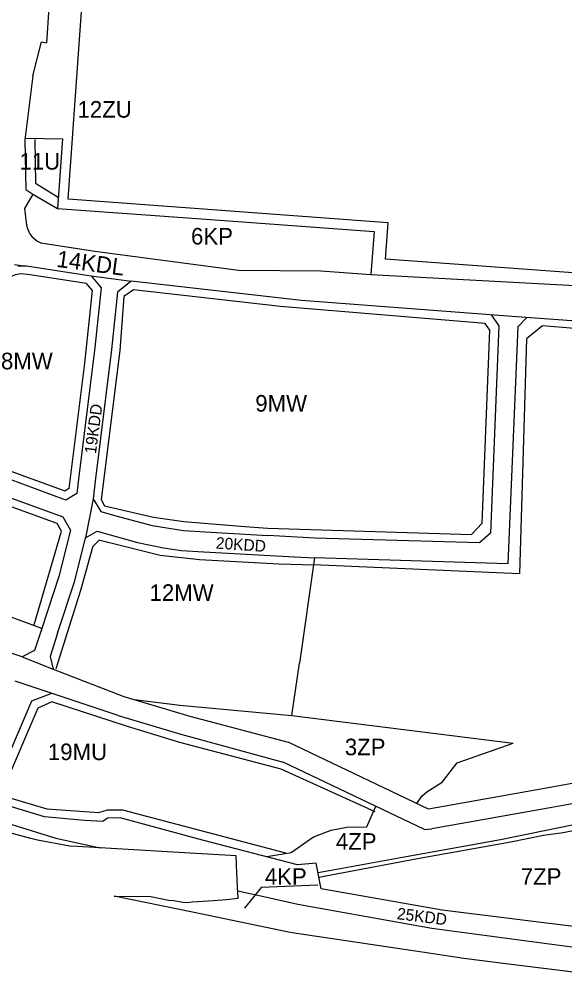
# Model space of a CAD drawing. Extents: x 7428203 to 7432868, y 5542672 to 5545406.
# Drawn here: x 7432004 to 7432333, y 5542818 to 5543396 of the extents above; entities that cross this region are included whole.
import ezdxf

# ---------------------------------------------------------------- set-up
doc = ezdxf.new("R2010")
doc.units = 0
for name, color, linetype in [('granica_planu', 7, 'Continuous'), ('linie_rozgraniczajace', 7, 'Continuous'), ('linie_zabudowy_nieprzekraczalne', 7, 'Continuous'), ('oznaczenia_przeznaczen', 7, 'Continuous')]:
    doc.layers.add(name, color=color, linetype=linetype)

msp = doc.modelspace()

# ---------------------------------------------------------------- linework, layer by layer
at = {"layer": 'granica_planu'}
msp.add_lwpolyline([(7432366.07, 5542818.36), (7432299.15, 5542826.68), (7432270.59, 5542830.22), (7432269.61, 5542830.37), (7432247.14, 5542833.74), (7432240.24, 5542834.78), (7432168.81, 5542845.49), (7432167.6, 5542845.74), (7432108.76, 5542857.84), (7432061.43, 5542867.58), (7432083.54, 5542867.28), (7432094.2, 5542865.19), (7432097.52, 5542864.92), (7432099.5, 5542864.5), (7432103.13, 5542863.99), (7432105.41, 5542863.84), (7432108.51, 5542864.06), (7432121.35, 5542864.94), (7432129.15, 5542865.52), (7432136.19, 5542866.32), (7432136, 5542870.15), (7432135.89, 5542872.37), (7432135.64, 5542878.11), (7432135.51, 5542881.51), (7432134.96, 5542891.84), (7432107.31, 5542893.48), (7432059.63, 5542896.3), (7432052.98, 5542896.69), (7432039.2, 5542897.51), (7432034.8, 5542897.77), (7432015.34, 5542901.29), (7432011.22, 5542902.36), (7431994.8, 5542906.65)], dxfattribs=at)
at = {"layer": 'linie_rozgraniczajace'}
for p, q in [((7432037.23, 5543621.26), (7432020.68, 5543381.69)), ((7432033.73, 5543287.48), (7432057.57, 5543619.82)), ((7432012.53, 5543361.9), (7432007.71, 5543323.27)), ((7432007.71, 5543323.27), (7432008.21, 5543293.28)), ((7432008.21, 5543293.28), (7432012.56, 5543290.59)), ((7432226.56, 5543273.31), (7432033.73, 5543287.48)), ((7432224.95, 5543251.39), (7432226.56, 5543273.31)), ((7432008.74, 5543271.82), (7432009.24, 5543269.81)), ((7432009.24, 5543269.81), (7432010.01, 5543267.87)), ((7432010.01, 5543267.87), (7432010.69, 5543266.65)), ((7432010.69, 5543266.65), (7432011.86, 5543265.07)), ((7432011.86, 5543265.07), (7432014.95, 5543262.4)), ((7432014.95, 5543262.4), (7432017.22, 5543261.23)), ((7432017.22, 5543261.23), (7432049.82, 5543256.21)), ((7432505.88, 5543230.9), (7432224.95, 5543251.39)), ((7432047.55, 5543241.39), (7432071.7, 5543238.19)), ((7432071.7, 5543238.19), (7432063.48, 5543231.48)), ((7432063.48, 5543231.48), (7432059.85, 5543196.95)), ((7432293.36, 5543211.37), (7432289.12, 5543217.69)), ((7432059.85, 5543196.95), (7432050.01, 5543117.61)), ((7432050.01, 5543117.61), (7432048.79, 5543107.04)), ((7432048.79, 5543107.04), (7432044.22, 5543083.37)), ((7432048.79, 5543107.04), (7432053.55, 5543099.39)), ((7432053.55, 5543099.39), (7432062.57, 5543096.75)), ((7432062.57, 5543096.75), (7432084.4, 5543090.89)), ((7432044.22, 5543083.37), (7432051.3, 5543087.55)), ((7432051.3, 5543087.55), (7432075.64, 5543080.66)), ((7432084.4, 5543090.89), (7432103.35, 5543087.86)), ((7432103.35, 5543087.86), (7432116.25, 5543087)), ((7432037.72, 5543057.46), (7432044.22, 5543083.37)), ((7432116.25, 5543087), (7432154.1, 5543084.92)), ((7432182.5, 5543083.35), (7432154.1, 5543084.92)), ((7432075.64, 5543080.66), (7432091.23, 5543077.48)), ((7432091.23, 5543077.48), (7432102.09, 5543075.91)), ((7432102.09, 5543075.91), (7432115.52, 5543075.02)), ((7432115.52, 5543075.02), (7432170.23, 5543072.01)), ((7432170.23, 5543072.01), (7432182.15, 5543071.36)), ((7432182.15, 5543071.36), (7432173.17, 5543007.95)), ((7432017.85, 5543028.79), (7431919, 5543064.95)), ((7432027.43, 5543025.93), (7432037.72, 5543057.46)), ((7432005.96, 5543011.7), (7432024.64, 5543004.41)), ((7432168.62, 5542976.37), (7432173.17, 5543007.95)), ((7432001.68, 5542997.32), (7432063.09, 5542976.74)), ((7432011.78, 5542985.25), (7432023.96, 5542989.85)), ((7431989.67, 5542933.23), (7432011.78, 5542985.25)), ((7432063.97, 5542976.44), (7432103.64, 5542964.58)), ((7432168.62, 5542976.37), (7432302.06, 5542959.76)), ((7432103.64, 5542964.58), (7432103.98, 5542964.48)), ((7432103.98, 5542964.48), (7432163.4, 5542948.38)), ((7432250.93, 5542919.95), (7432166.31, 5542960.28)), ((7432248.57, 5542907.78), (7432163.4, 5542948.38)), ((7432466.38, 5542946.5), (7432326.44, 5542921.16)), ((7432019.53, 5542915.43), (7431995.04, 5542922.73)), ((7432326.39, 5542921.15), (7432253.03, 5542908.13)), ((7432043.53, 5542913.22), (7432019.53, 5542915.43)), ((7432057.53, 5542914.56), (7432054.7, 5542912.58)), ((7432065.12, 5542914.7), (7432057.53, 5542914.56)), ((7432114.78, 5542901.27), (7432065.12, 5542914.7)), ((7432054.7, 5542912.58), (7432043.53, 5542913.22)), ((7432011.22, 5542902.36), (7431994.8, 5542906.65)), ((7432015.34, 5542901.29), (7432011.22, 5542902.36)), ((7432034.8, 5542897.77), (7432015.34, 5542901.29)), ((7432039.2, 5542897.51), (7432034.8, 5542897.77)), ((7432052.98, 5542896.69), (7432039.2, 5542897.51)), ((7432059.63, 5542896.3), (7432052.98, 5542896.69)), ((7432171.89, 5542886.38), (7432114.78, 5542901.27)), ((7432107.31, 5542893.48), (7432059.63, 5542896.3)), ((7432134.96, 5542891.84), (7432107.31, 5542893.48)), ((7432135.51, 5542881.51), (7432134.96, 5542891.84)), ((7432183.24, 5542887.35), (7432171.89, 5542886.38)), ((7432186.29, 5542871.95), (7432183.24, 5542887.35)), ((7432135.64, 5542878.11), (7432135.51, 5542881.51)), ((7432135.89, 5542872.37), (7432135.64, 5542878.11)), ((7432136, 5542870.15), (7432135.89, 5542872.37)), ((7432153.44, 5542866.78), (7432135.98, 5542870.54)), ((7432136.19, 5542866.32), (7432136, 5542870.15)), ((7432259.18, 5542859.04), (7432186.29, 5542871.95)), ((7432108.76, 5542857.84), (7432061.43, 5542867.58)), ((7432061.43, 5542867.58), (7432083.54, 5542867.28)), ((7432083.54, 5542867.28), (7432094.2, 5542865.19)), ((7432094.2, 5542865.19), (7432097.52, 5542864.92)), ((7432097.52, 5542864.92), (7432099.5, 5542864.5)), ((7432099.5, 5542864.5), (7432103.13, 5542863.99)), ((7432103.13, 5542863.99), (7432105.41, 5542863.84)), ((7432105.41, 5542863.84), (7432108.51, 5542864.06)), ((7432108.51, 5542864.06), (7432121.35, 5542864.94)), ((7432121.35, 5542864.94), (7432129.15, 5542865.52)), ((7432129.15, 5542865.52), (7432136.19, 5542866.32)), ((7432172.21, 5542862.58), (7432153.44, 5542866.78)), ((7432253.01, 5542848.01), (7432172.21, 5542862.58)), ((7432167.6, 5542845.74), (7432108.76, 5542857.84)), ((7432371.53, 5542845.19), (7432259.18, 5542859.04)), ((7432168.81, 5542845.49), (7432167.6, 5542845.74)), ((7432240.24, 5542834.78), (7432168.81, 5542845.49)), ((7432368.86, 5542832.71), (7432253.01, 5542848.01)), ((7432247.14, 5542833.74), (7432240.24, 5542834.78)), ((7432269.61, 5542830.37), (7432247.14, 5542833.74)), ((7432270.59, 5542830.22), (7432269.61, 5542830.37)), ((7432299.15, 5542826.68), (7432270.59, 5542830.22)), ((7432366.07, 5542818.36), (7432299.15, 5542826.68))]:
    msp.add_line(p, q, dxfattribs=at)
for points in [[(7432012.53, 5543361.9), (7432017.7, 5543382.28), (7432020.68, 5543381.69)], [(7432007.83, 5543324.19), (7432030.39, 5543323.92), (7432027.3, 5543281.94)], [(7432012.56, 5543290.59), (7432007.45, 5543281.86), (7432008.74, 5543271.82)], [(7432012.56, 5543290.59), (7432027.3, 5543281.94), (7432114.18, 5543275.56), (7432218.14, 5543267.92), (7432216.24, 5543242.02)], [(7432049.82, 5543256.21), (7432136.37, 5543244.64), (7432186.04, 5543244.35), (7432216.24, 5543242.02), (7432413.94, 5543231.48), (7432640.36, 5543214.85), (7432658.04, 5543210.49), (7432742.56, 5543204.3), (7432752.27, 5543212.93)], [(7432001.46, 5543248.23), (7432006.98, 5543247.37), (7432008.71, 5543247.29), (7432047.55, 5543241.39), (7432053.63, 5543234.02), (7432049.91, 5543198.06), (7432040.08, 5543118.81), (7432039.08, 5543110.11), (7432032.45, 5543106.16), (7431997.81, 5543118.94)], [(7432003.48, 5543247.42), (7432006.98, 5543247.37)], [(7432388.91, 5543210.14), (7432379.65, 5543211.02), (7432369.94, 5543211.73), (7432351.23, 5543213.11), (7432301.34, 5543216.75), (7432174.33, 5543226.52), (7432071.7, 5543238.19)], [(7432310.15, 5543216.11), (7432304.83, 5543210.52), (7432298.81, 5543067.88), (7432182.15, 5543071.36)], [(7432293.36, 5543211.37), (7432288.33, 5543086.28), (7432281.66, 5543080.39), (7432182.5, 5543083.35)], [(7431947.45, 5543143.42), (7431939.96, 5543122.74), (7431947.58, 5543126.31), (7432030.55, 5543096.2), (7432035.1, 5543088.13), (7432028.11, 5543060.23), (7432017.85, 5543028.79), (7432013.51, 5543015.49), (7432005.96, 5543011.7), (7431916.9, 5543041.85), (7431913.29, 5543049.4), (7431919, 5543064.95), (7431932.86, 5543102.67), (7431939.96, 5543122.74)], [(7432027.43, 5543025.93), (7432022.88, 5543011.96), (7432024.64, 5543004.41)], [(7432024.64, 5543004.41), (7432067.41, 5542987.94), (7432107.08, 5542976.08), (7432166.31, 5542960.28)], [(7432073.79, 5542986.03), (7432101.04, 5542982.71), (7432168.62, 5542976.37)], [(7432184.35, 5542881.75), (7432235.29, 5542890.99), (7432294.29, 5542901.7), (7432338.45, 5542910.71), (7432389.9, 5542920.66), (7432456.41, 5542933.52), (7432500.71, 5542941.8), (7432565.92, 5542953.99), (7432618.41, 5542964.35), (7432650.2, 5542970.62), (7432674.54, 5542974.93)], [(7432243.85, 5542923.32), (7432246.9, 5542927.86), (7432250.02, 5542930.35), (7432259.21, 5542936.21), (7432268.23, 5542947.98), (7432302.06, 5542959.76)], [(7432460.08, 5542957.66), (7432324.29, 5542932.96), (7432250.93, 5542919.95)], [(7432181.56, 5542903.12), (7432183.3, 5542903.84), (7432192.18, 5542907.3), (7432201.77, 5542909.09), (7432213.76, 5542909.39), (7432219.23, 5542921.76)], [(7432416.09, 5542923.14), (7432367.66, 5542913.04), (7432332.08, 5542905.7), (7432320.15, 5542904.09), (7432300.61, 5542900.16), (7432244.28, 5542890.06), (7432184.93, 5542878.81)], [(7431973.61, 5542918.72), (7432026.26, 5542902.45), (7432052.98, 5542896.69)], [(7432181.56, 5542903.12), (7432168.23, 5542893.61), (7432154.62, 5542891.46), (7432153.35, 5542891.21)], [(7432248.57, 5542907.78), (7432253.03, 5542908.13)]]:
    msp.add_lwpolyline(points, dxfattribs=at)
for centre, radius, start, end in [((7432067.2118, 5542987.39), 11.4198, 248.8423077, 253.5082723), ((7432326.4, 5542921.23), 0.0806, 262.8749837, 299.7448813)]:
    msp.add_arc(centre, radius, start, end, dxfattribs=at)
at = {"layer": 'linie_zabudowy_nieprzekraczalne'}
for p, q in [((7432013.71, 5543323.37), (7432014.15, 5543297)), ((7432048.55, 5543078.17), (7432052.39, 5543082.08)), ((7432089.14, 5543072.78), (7432052.3, 5543082.04)), ((7432048.58, 5543078.36), (7432041.14, 5543051.81)), ((7432112.85, 5543070.19), (7432089.14, 5543072.78)), ((7432160.69, 5543067.53), (7432112.85, 5543070.19)), ((7432181.81, 5543066.97), (7432160.69, 5543067.53)), ((7432041.14, 5543051.81), (7432026.29, 5543004.53))]:
    msp.add_line(p, q, dxfattribs=at)
for points in [[(7432014.04, 5543297.09), (7432027.79, 5543288.64)], [(7432034.39, 5543113.14), (7432043.73, 5543188.67), (7432048.44, 5543232.45), (7432044.91, 5543236.73), (7432009.4, 5543242.19), (7432005.32, 5543242.44), (7432001.75, 5543241.93), (7431999.15, 5543240.63), (7431997.6, 5543238.7), (7431987.79, 5543223.21), (7431977.48, 5543205.45), (7431967.63, 5543182.62), (7431959.31, 5543160.62), (7431953.35, 5543144.87), (7431955.89, 5543139.22), (7431979.8, 5543130.62), (7432031.84, 5543111.71), (7432034.42, 5543113.41)], [(7432411.3, 5543203.48), (7432319.63, 5543211.15), (7432310.08, 5543203.33), (7432305.74, 5543061.76), (7432181.54, 5543067.1)], [(7432013.15, 5543030.51), (7432029.77, 5543087.41), (7432027.1, 5543092.15), (7431947.8, 5543120.89), (7431943.97, 5543119.1), (7431923.69, 5543063.23)], [(7432023.88, 5542984.66), (7432015.52, 5542980.91), (7431995.17, 5542933.46), (7431998.58, 5542926.78), (7432020.96, 5542920.22), (7432052.26, 5542917.94), (7432057.44, 5542919.56), (7432066.42, 5542919.52), (7432164.7, 5542893.58)], [(7432218.86, 5542918.3), (7432162.21, 5542944.02), (7432101.13, 5542960.09), (7432069.56, 5542969.75), (7432023.88, 5542984.66)]]:
    msp.add_lwpolyline(points, dxfattribs=at)
msp.add_lwpolyline([(7432053.75, 5543106.47), (7432055.72, 5543102.67), (7432085.19, 5543095.83), (7432103.48, 5543093.3), (7432140.28, 5543090.36), (7432154.01, 5543089.22), (7432276.93, 5543085.54), (7432283.33, 5543092.2), (7432287.98, 5543208.54), (7432284.99, 5543212.49), (7432161.65, 5543222.82), (7432073.06, 5543232.83), (7432067.26, 5543228.78), (7432064.81, 5543196.33)], close=True, dxfattribs=at)
at = {"layer": 'oznaczenia_przeznaczen'}
msp.add_lwpolyline([(7432184.16, 5542874.26), (7432150.11, 5542872.87), (7432139.96, 5542860.39)], dxfattribs=at)

# ---------------------------------------------------------------- texts
for s, p in [('12ZU', (7432039.3928, 5543336.61)), ('11U', (7432004.4309, 5543305.3)), ('6KP', (7432107.8142, 5543260.16)), ('8MW', (7431993.2869, 5543184.98)), ('9MW', (7432146.5469, 5543159.49)), ('12MW', (7432082.8137, 5543045.45)), ('3ZP', (7432200.489, 5542952.45)), ('19MU', (7432021.5532, 5542949.53)), ('4ZP', (7432195.099, 5542895.52)), ('4KP', (7432152.2942, 5542874.4)), ('7ZP', (7432306.549, 5542874.4))]:
    msp.add_text(s, height=10, dxfattribs=at).set_placement(p)
for s, height, rotation, p in [('14KDL', 10, 352.4526164, (7432026.3974, 5543246.7439)), ('19KDD', 7, 82.4478213, (7432050.4932, 5543133.7209)), ('20KDD', 7, 356.1356322, (7432122.6098, 5543076.9714)), ('25KDD', 7, 352.8155805, (7432231.6383, 5542853.7493))]:
    msp.add_text(s, height=height, rotation=rotation, dxfattribs=at).set_placement(p)

doc.saveas('drawing.dxf')
